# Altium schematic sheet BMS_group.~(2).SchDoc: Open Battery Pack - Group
size A3; Author: Morgane Vallée; Revision: 1.0; SheetNumber: 2; SheetTotal: 3
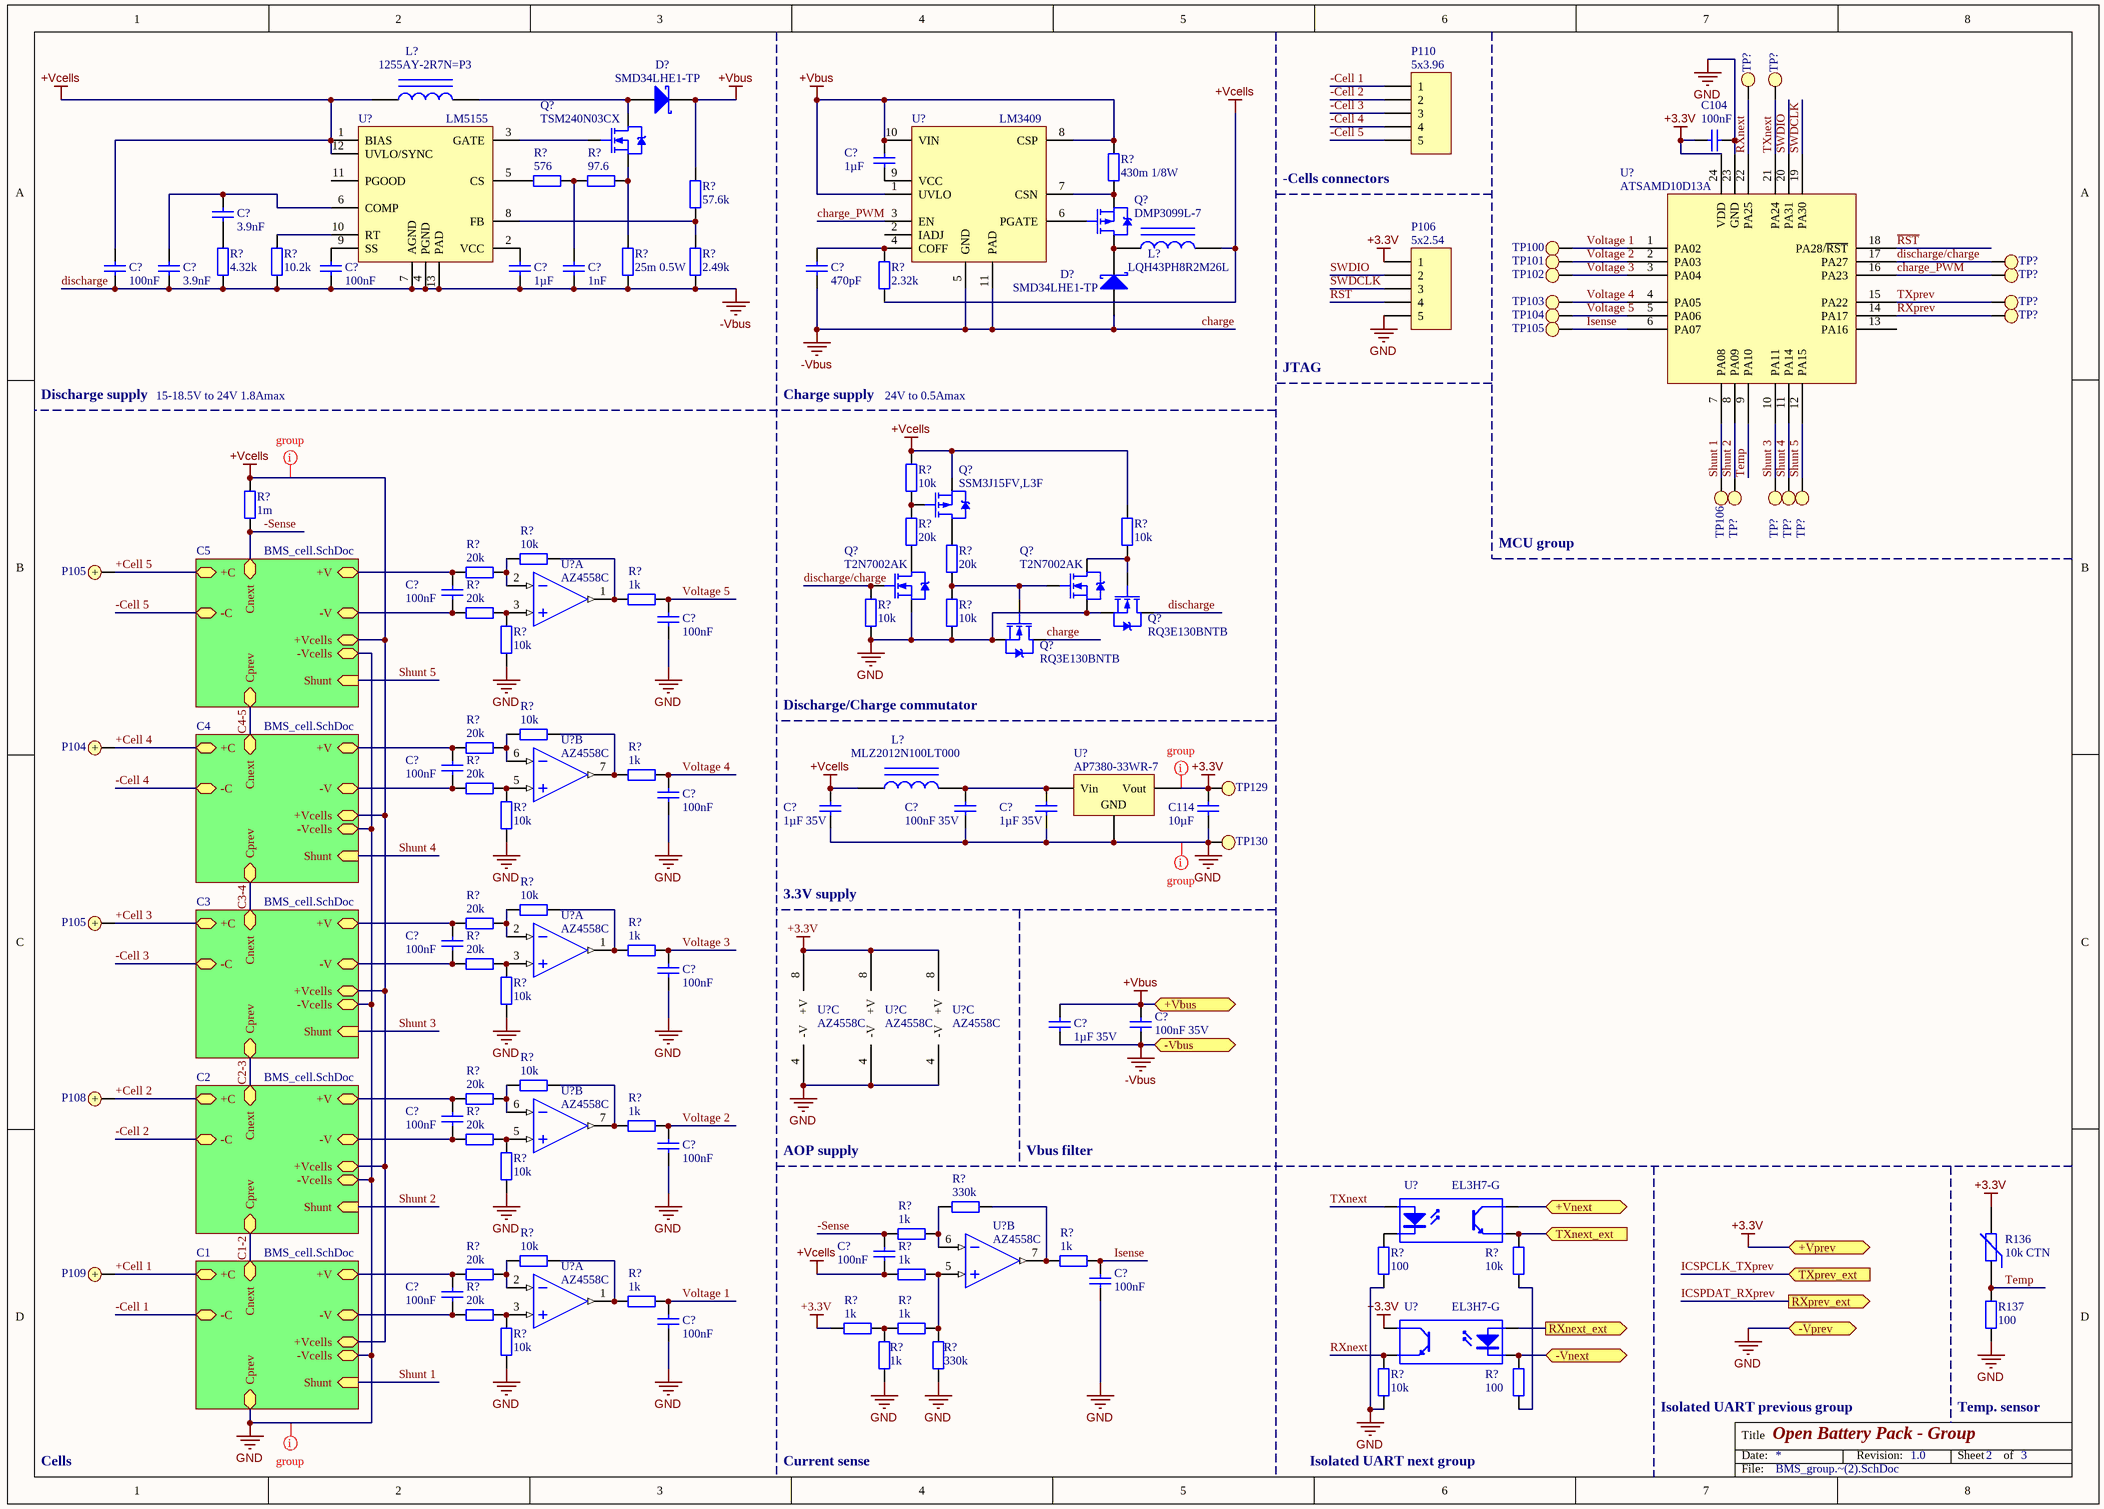
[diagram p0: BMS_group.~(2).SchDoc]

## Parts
(Parts that share a designator on the sheet are numbered #1, #2 ... from top to bottom, then left to right.)
C104  100nF  [C0603]
C114  10µF  [C0603]
C?#1  1µF  [C0603]
C?#2  3.9nF  [C0603]
C?#3  100nF  [C0603]
C?#4  3.9nF  [C0603]
C?#5  100nF  [C0603]
C?#6  1µF  [C0603]
C?#7  1nF  [C0603]
C?#8  470pF  [C0603]
C?#9  100nF  [C0603]
C?#10  100nF  [C0603]
C?#11  100nF  [C0603]
C?#12  100nF  [C0603]
C?#13  1µF 35V  [C0603]
C?#14  100nF 35V  [C0603]
C?#15  1µF 35V  [C0603]
C?#16  100nF  [C0603]
C?#17  100nF  [C0603]
C?#18  1µF 35V  [C0603]
C?#19  100nF 35V  [C0603]
C?#20  100nF  [C0603]
C?#21  100nF  [C0603]
C?#22  100nF  [C0603]
C?#23  100nF  [C0603]
C?#24  100nF  [C0603]
C?#25  100nF  [C0603]
D?#1  SMD34LHE1-TP  [SOT-23_N]
D?#2  SMD34LHE1-TP  [SOT-23_N]
L?#1  1255AY-2R7N=P3  [AXIAL-0.9]
L?#2  LQH43PH8R2M26L  [AXIAL-0.9]
L?#3  MLZ2012N100LT000  [AXIAL-0.9]
P104  Bat+  [Keystone 241]  (value not drawn)
P105#1  Bat+  [Keystone 241]  (value not drawn)
P105#2  Bat+  [Keystone 241]  (value not drawn)
P106  5x2.54  [HDR1X5]
P108  Bat+  [Keystone 241]  (value not drawn)
P109  Bat+  [Keystone 241]  (value not drawn)
P110  5x3.96  [HDR1X5]
Q?#1  TSM240N03CX  [DIODES SOT-23-3]
Q?#2  DMP3099L-7  [DIODES SOT-23-3]
Q?#3  SSM3J15FV,L3F  [DIODES SOT-23-3]
Q?#4  T2N7002AK  [DIODES SOT-23-3]
Q?#5  T2N7002AK  [DIODES SOT-23-3]
Q?#6  RQ3E130BNTB  [DIODES SOT-23-3]
Q?#7  RQ3E130BNTB  [DIODES SOT-23-3]
R136  10k CTN  [NTC]
R137  100  [R0603]
R?#1  430m 1/8W  [R0603]
R?#2  576  [R0603]
R?#3  97.6  [R0603]
R?#4  57.6k  [R0603]
R?#5  2.32k  [R0603]
R?#6  4.32k  [R0603]
R?#7  10.2k  [R0603]
R?#8  25m 0.5W  [R0603]
R?#9  2.49k  [R0603]
R?#10  10k  [R0603]
R?#11  1m  [R0603]
R?#12  10k  [R0603]
R?#13  20k  [R0603]
R?#14  10k  [R0603]
R?#15  20k  [R0603]
R?#16  20k  [R0603]
R?#17  1k  [R0603]
R?#18  20k  [R0603]
R?#19  10k  [R0603]
R?#20  10k  [R0603]
R?#21  10k  [R0603]
R?#22  10k  [R0603]
R?#23  20k  [R0603]
R?#24  1k  [R0603]
R?#25  20k  [R0603]
R?#26  10k  [R0603]
R?#27  10k  [R0603]
R?#28  20k  [R0603]
R?#29  1k  [R0603]
R?#30  20k  [R0603]
R?#31  10k  [R0603]
R?#32  10k  [R0603]
R?#33  20k  [R0603]
R?#34  1k  [R0603]
R?#35  20k  [R0603]
R?#36  10k  [R0603]
R?#37  1k  [R0603]
R?#38  330k  [R0603]
R?#39  10k  [R0603]
R?#40  10k  [R0603]
R?#41  20k  [R0603]
R?#42  1k  [R0603]
R?#43  100  [R0603]
R?#44  1k  [R0603]
R?#45  1k  [R0603]
R?#46  20k  [R0603]
R?#47  10k  [R0603]
R?#48  1k  [R0603]
R?#49  1k  [R0603]
R?#50  1k  [R0603]
R?#51  330k  [R0603]
R?#52  100  [R0603]
R?#53  10k  [R0603]
TP100  Test Point  [Test Point]  (value not drawn)
TP101  Test Point  [Test Point]  (value not drawn)
TP102  Test Point  [Test Point]  (value not drawn)
TP103  Test Point  [Test Point]  (value not drawn)
TP104  Test Point  [Test Point]  (value not drawn)
TP105  Test Point  [Test Point]  (value not drawn)
TP106  Test Point  [Test Point]  (value not drawn)
TP129  Test Point  [Test Point]  (value not drawn)
TP130  Test Point  [Test Point]  (value not drawn)
TP?#1  Test Point  [Test Point]  (value not drawn)
TP?#2  Test Point  [Test Point]  (value not drawn)
TP?#3  Test Point  [Test Point]  (value not drawn)
TP?#4  Test Point  [Test Point]  (value not drawn)
TP?#5  Test Point  [Test Point]  (value not drawn)
TP?#6  Test Point  [Test Point]  (value not drawn)
TP?#7  Test Point  [Test Point]  (value not drawn)
TP?#8  Test Point  [Test Point]  (value not drawn)
TP?#9  Test Point  [Test Point]  (value not drawn)
TP?#10  Test Point  [Test Point]  (value not drawn)
U?#1  LM5155  [TI MSOP-10 DGQ]
U?#2  LM3409  [TI MSOP-10 DGQ]
U?#3  ATSAMD10D13A  [SMSC QFN-24 4x4MM]
U?#4  AZ4558C  [DIODES SO-8]  (part A of 3)
U?#5  AZ4558C  [DIODES SO-8]  (part B of 3)
U?#6  AP7380-33WR-7  [DIODES SOT-23-5 W5]
U?#7  AZ4558C  [DIODES SO-8]  (part A of 3)
U?#8  AZ4558C  [DIODES SO-8]  (part C of 3)
U?#9  AZ4558C  [DIODES SO-8]  (part C of 3)
U?#10  AZ4558C  [DIODES SO-8]  (part C of 3)
U?#11  AZ4558C  [DIODES SO-8]  (part B of 3)
U?#12  EL3H7-G  [OPTO_EL3H7-G]
U?#13  AZ4558C  [DIODES SO-8]  (part B of 3)
U?#14  AZ4558C  [DIODES SO-8]  (part A of 3)
U?#15  EL3H7-G  [OPTO_EL3H7-G]

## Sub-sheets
C1 = BMS_cell.SchDoc: -C, -V, +C, +Vcells, Cnext, -Vcells, +V, Shunt (in), Cprev
C2 = BMS_cell.SchDoc: -C, -V, +C, +Vcells, Cnext, -Vcells, +V, Shunt (in), Cprev
C3 = BMS_cell.SchDoc: -C, -V, +C, +Vcells, Cnext, -Vcells, +V, Shunt (in), Cprev
C4 = BMS_cell.SchDoc: -C, -V, +C, +Vcells, Cnext, -Vcells, +V, Shunt (in), Cprev
C5 = BMS_cell.SchDoc: -C, -V, +C, +Vcells, Cnext, -Vcells, +V, Shunt (in), Cprev

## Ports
+Vbus, +Vnext, +Vprev, -Vbus, -Vnext, -Vprev, RXnext_ext (out), RXprev_ext (out), TXnext_ext (in), TXprev_ext (in)

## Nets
+3.3V: C104.2 C114.1 P106.1 R136.2 R?#48.2 TP129.1 U?#3.24(VDD) U?#6.3(Vout) U?#8.8(+V) U?#9.8(+V) U?#10.8(+V) U?#15.4(C) ; port +Vprev
+Vbus: C?#1.1 C?#18.1 C?#19.1 D?#1.3(K) R?#1.2 R?#4.2 U?#2.1(UVLO) U?#2.8(CSP) U?#2.10(VIN) ; port +Vbus
+Vcells: C?#3.1 C?#13.1 C?#22.2 L?#1.1 L?#2.2 L?#3.1 Q?#3.2(S) R?#5.2 R?#10.2 R?#11.2 R?#14.2 R?#44.2 U?#1.1(BIAS) U?#1.12(UVLO/SYNC) ; sheet C1/+Vcells, sheet C2/+Vcells, sheet C3/+Vcells, sheet C4/+Vcells, sheet C5/+Vcells
charge: C?#3.2 C?#4.2 C?#5.2 C?#6.2 C?#7.2 C?#8.2 C?#18.2 C?#19.2 D?#2.1(A) Q?#6.3(D) Q?#7.3(D) R?#6.1 R?#7.1 R?#8.1 R?#9.1 U?#1.4(PGND) U?#1.7(AGND) U?#1.13(PAD) U?#2.5(GND) U?#2.11(PAD) ; port -Vbus  [also labelled -Vbus, discharge]
GND: C104.1 C114.2 C?#10.2 C?#12.2 C?#13.2 C?#14.2 C?#15.2 C?#17.2 C?#21.2 C?#23.2 C?#25.2 P106.5 Q?#4.2(S) Q?#5.2(S) Q?#6.2(S) Q?#7.2(S) R137.2 R?#19.2 R?#20.1 R?#21.1 R?#26.2 R?#31.2 R?#36.2 R?#43.1 R?#47.2 R?#49.2 R?#51.1 R?#53.1 TP130.1 U?#3.23(GND) U?#6.2(GND) U?#8.4(-V) U?#9.4(-V) U?#10.4(-V) ; port -Vprev, sheet C1/-Vcells, sheet C1/Cprev, sheet C2/-Vcells, sheet C3/-Vcells, sheet C4/-Vcells, sheet C5/-Vcells
+Cell 1: P109.1 ; sheet C1/+C
+Cell 2: P108.1 ; sheet C2/+C
+Cell 3: P105#2.1 ; sheet C3/+C
+Cell 4: P104.1 ; sheet C4/+C
+Cell 5: P105#1.1 ; sheet C5/+C
+Vnext: U?#12.4(C) ; port +Vnext
-Cell 1: P110.1 ; sheet C1/-C
-Cell 2: P110.2 ; sheet C2/-C
-Cell 3: P110.3 ; sheet C3/-C
-Cell 4: P110.4 ; sheet C4/-C
-Cell 5: P110.5 ; sheet C5/-C
-Sense: C?#22.1 R?#11.1 R?#37.1 ; sheet C5/Cnext
-Vnext: R?#52.1 U?#15.2(K) ; port -Vnext
C1-2: sheet C1/Cnext, sheet C2/Cprev
C2-3: sheet C2/Cnext, sheet C3/Cprev
C3-4: sheet C3/Cnext, sheet C4/Cprev
C4-5: sheet C4/Cnext, sheet C5/Cprev
charge_PWM: TP?#4.1 U?#2.3(EN) U?#3.16(PA23)
discharge/charge: Q?#4.1(G) R?#20.2 TP?#3.1 U?#3.17(PA27)
Isense: C?#23.1 R?#42.1 TP105.1 U?#3.6(PA07)
~{RST}: P106.4 U?#3.18(PA28/~{RST})
RXnext: R?#53.2 TP?#1.1 U?#3.22(PA25) U?#15.3(E)
RXnext_ext: U?#15.1(A) ; port RXnext_ext
RXprev: TP?#6.1 U?#3.14(PA17)
Shunt 1: TP106.1 U?#3.7(PA08) ; sheet C1/Shunt
Shunt 2: TP?#7.1 U?#3.8(PA09) ; sheet C2/Shunt
Shunt 3: TP?#8.1 U?#3.10(PA11) ; sheet C3/Shunt
Shunt 4: TP?#9.1 U?#3.11(PA14) ; sheet C4/Shunt
Shunt 5: TP?#10.1 U?#3.12(PA15) ; sheet C5/Shunt
SWDCLK: P106.3 U?#3.19(PA30)
SWDIO: P106.2 U?#3.20(PA31)
Temp: R136.1 R137.1 U?#3.9(PA10)
TXnext: TP?#2.1 U?#3.21(PA24) U?#12.1(A)
TXnext_ext: R?#40.1 U?#12.3(E) ; port TXnext_ext
TXprev: TP?#5.1 U?#3.15(PA22)
Voltage 1: C?#25.1 R?#45.1 TP100.1 U?#3.1(PA02)
Voltage 2: C?#21.1 R?#34.1 TP101.1 U?#3.2(PA03)
Voltage 3: C?#17.1 R?#29.1 TP102.1 U?#3.3(PA04)
Voltage 4: C?#12.1 R?#24.1 TP103.1 U?#3.4(PA05)
Voltage 5: C?#10.1 R?#17.1 TP104.1 U?#3.5(PA06)
NetC?#1_2: C?#1.2 U?#2.9(VCC)
NetC?#2_1: C?#2.1 C?#4.1 U?#1.6(COMP)
NetC?#2_2: C?#2.2 R?#6.2
NetC?#5_1: C?#5.1 U?#1.9(SS)
NetC?#6_1: C?#6.1 U?#1.2(VCC)
NetC?#7_1: C?#7.1 R?#2.1 R?#3.2
NetC?#8_1: C?#8.1 R?#5.1 U?#2.4(COFF)
NetC?#9_1: C?#9.1 R?#15.1 ; sheet C5/+V
NetC?#9_2: C?#9.2 R?#18.2 ; sheet C5/-V
NetC?#11_1: C?#11.1 R?#23.1 ; sheet C4/+V
NetC?#11_2: C?#11.2 R?#25.2 ; sheet C4/-V
NetC?#14_1: C?#14.1 C?#15.1 L?#3.2 U?#6.1(Vin)
NetC?#16_1: C?#16.1 R?#28.1 ; sheet C3/+V
NetC?#16_2: C?#16.2 R?#30.2 ; sheet C3/-V
NetC?#20_1: C?#20.1 R?#33.1 ; sheet C2/+V
NetC?#20_2: C?#20.2 R?#35.2 ; sheet C2/-V
NetC?#24_1: C?#24.1 R?#41.1 ; sheet C1/+V
NetC?#24_2: C?#24.2 R?#46.2 ; sheet C1/-V
NetD?#1_1: D?#1.1(A) L?#1.2 Q?#1.3(D)
NetD?#2_3: D?#2.3(K) L?#2.1 Q?#2.3(D)
NetQ?#1_1: Q?#1.1(G) U?#1.3(GATE)
NetQ?#1_2: Q?#1.2(S) R?#3.1 R?#8.2
NetQ?#2_1: Q?#2.1(G) U?#2.6(PGATE)
NetQ?#2_2: Q?#2.2(S) R?#1.1 U?#2.7(CSN)
NetQ?#3_1: Q?#3.1(G) R?#10.1 R?#13.2
NetQ?#3_3: Q?#3.3(D) R?#16.2
NetQ?#4_3: Q?#4.3(D) R?#13.1
NetQ?#5_1: Q?#5.1(G) Q?#7.1(G) R?#16.1 R?#21.2
NetQ?#5_3: Q?#5.3(D) Q?#6.1(G) R?#14.1
NetR?#2_2: R?#2.2 U?#1.5(CS)
NetR?#4_1: R?#4.1 R?#9.2 U?#1.8(FB)
NetR?#7_2: R?#7.2 U?#1.10(RT)
NetR?#12_1: R?#12.1 R?#15.2 U?#4.2(IN-)
NetR?#12_2: R?#12.2 R?#17.2 U?#4.1(OUT)
NetR?#18_1: R?#18.1 R?#19.1 U?#4.3(IN+)
NetR?#22_1: R?#22.1 R?#23.2 U?#5.6(IN-)
NetR?#22_2: R?#22.2 R?#24.2 U?#5.7(OUT)
NetR?#25_1: R?#25.1 R?#26.1 U?#5.5(IN+)
NetR?#27_1: R?#27.1 R?#28.2 U?#7.2(IN-)
NetR?#27_2: R?#27.2 R?#29.2 U?#7.1(OUT)
NetR?#30_1: R?#30.1 R?#31.1 U?#7.3(IN+)
NetR?#32_1: R?#32.1 R?#33.2 U?#11.6(IN-)
NetR?#32_2: R?#32.2 R?#34.2 U?#11.7(OUT)
NetR?#35_1: R?#35.1 R?#36.1 U?#11.5(IN+)
NetR?#37_2: R?#37.2 R?#38.2 U?#13.6(IN-)
NetR?#38_1: R?#38.1 R?#42.2 U?#13.7(OUT)
NetR?#39_1: R?#39.1 R?#41.2 U?#14.2(IN-)
NetR?#39_2: R?#39.2 R?#45.2 U?#14.1(OUT)
NetR?#40_2: R?#40.2 R?#52.2
NetR?#43_2: R?#43.2 U?#12.2(K)
NetR?#44_1: R?#44.1 R?#50.1 R?#51.2 U?#13.5(IN+)
NetR?#46_1: R?#46.1 R?#47.1 U?#14.3(IN+)
NetR?#48_1: R?#48.1 R?#49.1 R?#50.2

Not connected (* = marked no-connect by the designer): U?#1 11(PGOOD); U?#2 2(IADJ); U?#3 13(PA16)

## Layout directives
net class Group: +3.3V, +Vcells, GND

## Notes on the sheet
- (near P110) -Cells connectors
- JTAG
- Discharge supply
- 15-18.5V to 24V 1.8Amax
- Charge supply
- 24V to 0.5Amax
- MCU group
- Discharge/Charge commutator
- 3.3V supply
- AOP supply
- Vbus filter
- Isolated UART previous group
- Temp. sensor
- Cells
- Current sense
- Isolated UART next group

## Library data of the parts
C104 C114 C?#1-C?#25 = Cap: Capacitor
D?#1 D?#2 = Diode BAT17
L?#1-L?#3 = Inductor Iron: Magnetic-Core Inductor
P104 P105#1 P105#2 P108 P109 = Bat+: Battery contact +
P106 P110 = Header 5: Header, 5-Pin
Q?#1 Q?#4-Q?#7 = MOSFET_N
Q?#2 Q?#3 = MOSFET_P
R136 = Res Varistor: Varistor (Voltage-Sensitive Resistor)
R137 R?#1-R?#53 = Res2: Resistor
U?#1 = LM5155: 2.2-MHz Wide Input Nonsynchronous Boost, SEPIC, Flyback Controller
U?#2 = LM3409: P-FET Buck Controller for High-Power LED Drivers
U?#4 U?#5 U?#7-U?#11 U?#13 U?#14 = LM2904: Low-power dual operational amplifiers
U?#6 = Volt Reg: Voltage Regulator
U?#12 U?#15 = Optoisolator1: 4-Pin Phototransistor Optocoupler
